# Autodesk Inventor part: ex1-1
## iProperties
Author: Administrator
Created: 2001-09
Part Number: ex1-1
Document SubType Name: Modeling
Designer: Administrator
Control State: 0
Master: False
Checked Out: False
PropertySet Name: Design Tracking Control
Length Units: 11272
Angle Units: 11279
Time Units: 11290
Mass Units: 11286
Shininess: 3
Angle Display Precision: 2
Document Length Units: 11272
Document Angle Units: 11286
Document Time Units: 11279
Document Mass Units: 11290
Document Length Units Precision: 3
Document Angle Units Precision: 2
Compacted: False
PropertySet Name: _Private Model Information
Density: 0.0
Volumn: 0.0
Area: 0.0
PropertySet Name: Model Information
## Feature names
1. Extrusion1
